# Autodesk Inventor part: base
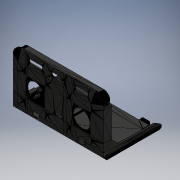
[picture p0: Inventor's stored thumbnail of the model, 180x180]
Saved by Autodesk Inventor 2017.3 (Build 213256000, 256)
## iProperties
Part Number: base
Material: Générique
Document SubType Name: Modeling
Designer: ficho
Density: 1 g/cm^3
Appearance: Par défaut
Author: ficho
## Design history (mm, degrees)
node "base"
  node "FonctionMaillage1"
